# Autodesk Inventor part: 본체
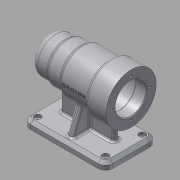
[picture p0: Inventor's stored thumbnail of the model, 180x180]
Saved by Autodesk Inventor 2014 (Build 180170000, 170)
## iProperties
Created: 2016-06
Part Number: 본체
Material: 알루미늄 6061
Document SubType Name: Modeling
Designer: SCD-A13
Density: 2.71 g/cm^3
Appearance: 알루미늄 - 평지
Mass: 672.126 g
Surface Area: 649.425 cm^2
Volume: 248.017 cm^3
Author: SCD-A13
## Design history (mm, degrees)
sketch "스케치1"
  geometry: L1 (-56, 35)-(56, 35); L2 (56, 35)-(56, -35); L3 (56, -35)-(-56, -35); L4 (-56, -35)-(-56, 35); 3 further points
  constraints: 8 end point, 2 midpoint, 2 parallel, 1 horizontal, 1 horizontal alignment, 1 perpendicular, 1 vertical alignment
  dimensions: "d0" = 70 distance of L1.end L2.end; "d1" = 112 distance of L1.start L1.end
extrude "돌출1" new body sketch "스케치1" distance "d2" = 10; taper "d3" = 0 deg
fillet "모깎기1" dims "d4" = 10
sketch "스케치2"
  geometry: A1 r 10 centre (-46, 25) between (-46, 35) and (-56, 25) reference; A2 r 10 centre (-46, -25) between (-56, -25) and (-46, -35) reference; A3 r 10 centre (46, -25) between (46, -35) and (56, -25) reference; A4 r 10 centre (46, 25) between (56, 25) and (46, 35) reference; 1 further point
hole "구멍1" sketch "스케치2" at (-46, 25), (-46, -25), (46, -25), (46, 25) diameter "d5" = 5; stored, may be unused: countersink angle "d9" = 90 deg, drill point angle "d11" = 118 deg; dims "d6" = 6, "d7" = 9, "d8" = 4, "d10" = 8
sketch "스케치3"
  geometry: L1 (56, 10)-(56, 0) reference; L2 (56, 0)-(-56, 0) reference; L3 (-56, 0)-(-56, 10) reference; L4 (-56, 10)-(56, 10) reference; L5 (56, 70)-(-56, 70); L6 (-56, 70)-(-56, 104); L7 (-56, 104)-(-28, 104); L8 (-28, 104)-(-28, 100); L9 (-28, 100)-(11, 100); L10 (11, 100)-(11, 97); L11 (11, 97)-(31, 97); L12 (31, 97)-(31, 95); L13 (31, 95)-(56, 95); L14 (56, 95)-(56, 70); 1 further point
  constraints: 20 end point, 9 parallel, 1 perpendicular, 1 vertical alignment
  dimensions: "d12" = 112 distance of L5.start L5.end; "d13" = 25 distance of L13.end L5.start; "d14" = 34 distance of L5.end L6.end; "d15" = 25 distance of L12.end L13.end; "d16" = 45 distance between parallel lines of L10 L14; "d17" = 84 distance between parallel lines of L8 L14; "d18" = 27 distance between parallel lines of L5 L11; "d19" = 30 distance between parallel lines of L5 L9; "d20" = 70 distance between parallel lines of L2 L5
revolve "회전1" sketch "스케치3" stored, may be unused: angle "d21" = 90 deg
sketch "스케치4"
  geometry: L1 (56, 25)-(56, -25) reference; L2 (46, -35)-(-46, -35) reference; L3 (-56, -25)-(-56, 25) reference; L4 (-46, 35)-(46, 35) reference; L5 (-36, -4)-(36, -4); L6 (36, -4)-(36, 4); L7 (36, 4)-(-36, 4); L8 (-36, 4)-(-36, -4); C1 r 4.5 at (46, -25) reference; C2 r 4.5 at (-46, 25) reference; C3 r 4.5 at (-46, -25) reference; C4 r 4.5 at (46, 25) reference; A1 r 10 centre (46, 25) between (56, 25) and (46, 35) reference; A2 r 10 centre (46, -25) between (46, -35) and (56, -25) reference; A3 r 10 centre (-46, -25) between (-56, -25) and (-46, -35) reference; A4 r 10 centre (-46, 25) between (-46, 35) and (-56, 25) reference; 2 further points
  constraints: 8 end point, 2 parallel, 1 horizontal, 1 midpoint, 1 perpendicular, 1 vertical alignment
  dimensions: "d22" = 72 distance of L6.end L7.end; "d23" = 8 distance of L7.end L5.start; "d24" = 4 distance from line of point (0, 0) L7
extrude "돌출2" join sketch "스케치4" stored distance "d25" = 10; taper "d26" = 0 deg
sketch "스케치5"
  geometry: L1 (-4, -28)-(4, -28); L2 (4, -28)-(4, 28); L3 (4, 28)-(-4, 28); L4 (-4, 28)-(-4, -28); 2 further points
  constraints: 8 end point, 2 parallel, 1 horizontal, 1 horizontal alignment, 1 midpoint, 1 perpendicular
  dimensions: "d27" = 8 distance of L2.end L3.end; "d28" = 56 distance of L3.end L1.start; "d29" = 4 distance from line of point (0, 0) L4
extrude "돌출3" new body sketch "스케치5" distance "d30" = 50; taper "d31" = 0 deg
feature "면 기울기1" dims angle "d32" = 20 deg
feature "면 기울기2" dims angle "d33" = 20 deg
feature "결합1"
  node "솔리드2"
hole "구멍2" diameter "d36" = 42; stored, may be unused: countersink angle "d40" = 90 deg, drill point angle "d42" = 0 deg; dims "d34" = 10, "d35" = 10, "d37" = 6, "d38" = 9, "d39" = 4, "d41" = 15
hole "구멍3" diameter "d45" = 42; stored, may be unused: countersink angle "d49" = 90 deg, drill point angle "d51" = 0 deg; dims "d43" = 10, "d44" = 10, "d46" = 6, "d47" = 48, "d48" = 54, "d50" = 66
hole "구멍4" diameter "d54" = 32; stored, may be unused: countersink angle "d58" = 90 deg, drill point angle "d60" = 0 deg; dims "d52" = 10, "d53" = 10, "d55" = 6, "d56" = 35, "d57" = 18, "d59" = 22
hole "구멍5" diameter "d63" = 21; stored, may be unused: countersink angle "d67" = 90 deg, drill point angle "d69" = 0 deg; dims "d61" = 10, "d62" = 10, "d64" = 6, "d65" = 35, "d66" = 18, "d68" = 3
sketch "스케치6"
  geometry: L1 (0, 0)-(-26, 0); C1 r 34 at (0, 0) reference; 1 further point
  constraints: 2 end point, 1 horizontal
  dimensions: "d70" = 26 distance of L1.start L1.end
hole "구멍6" sketch "스케치6" at (-26, 0) diameter "d71" = 3.242; stored, may be unused: countersink angle "d75" = 90 deg, drill point angle "d77" = 118 deg; dims "d72" = 8, "d73" = 35, "d74" = 18, "d76" = 11
sketch "스케치7"
  geometry: L1 (92, 0)-(0, 0) reference; L2 (102, 104)-(102, 36) reference; L3 (74, 36.236)-(74, 36.236) reference; L4 (74, 36.236)-(82, 36.236) reference; L5 (82, 36.236)-(82, 36.236) reference; L6 (82, 36.236)-(74, 36.236) reference; 2 further points
  constraints: 1 other
  dimensions: "d81" = 48 distance from line of L2 point (54, 70); "d82" = 70 distance from line of L1 point (54, 70)
feature "엠보싱1" sketch "스케치7" dims "d0" = 70, "d1" = 112, "d5" = 5, "d83" = 0.5, "d84" = 0
fillet "모깎기2" dims "d85" = 3, "d86" = 10
chamfer "모따기1" distance "d87" = 4; stored, may be unused: second distance "d88" = 2, angle "d89" = 45 deg
fillet "모깎기8" dims "d95" = 0.3, "d96" = 3
fillet "모깎기3" dims "d90" = 3
fillet "모깎기4" dims "d91" = 3
fillet "모깎기5" dims "d92" = 3
fillet "모깎기6" dims "d93" = 3
fillet "모깎기7" dims "d94" = 2
chamfer "모따기2" distance "d97" = 1; stored, may be unused: second distance "d98" = 2, angle "d99" = 45 deg
fillet "모깎기9" dims "d100" = 3
node "솔리드1"
pattern_circular "원형 패턴1" dims angle "d79" = 360 deg
node "투영된 루프1"
node "절단 모서리 투영1"
node "절단 모서리 투영2"
